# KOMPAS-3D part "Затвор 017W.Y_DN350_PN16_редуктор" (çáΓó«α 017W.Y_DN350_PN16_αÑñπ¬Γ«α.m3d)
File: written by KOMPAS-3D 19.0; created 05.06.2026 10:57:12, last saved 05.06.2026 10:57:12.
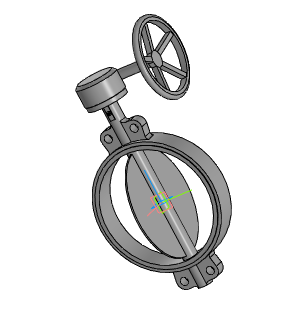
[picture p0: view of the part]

Document properties: Автор: Энергия; Полное имя файла: ..\..\..\3d для проектировщиков\x.x Тип 017W.Y(S) Затвор дисковый поворотный межфланцевый\Затвор 017W.Y(S)_DN50-DN1200_редуктор\Затвор 017W.Y_DN350_PN16_редуктор.a3d

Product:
- Part/product: Затвор 017W.Y_DN350_PN16_редуктор
    Масса: 40.5017

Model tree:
1. Операция без истории:1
